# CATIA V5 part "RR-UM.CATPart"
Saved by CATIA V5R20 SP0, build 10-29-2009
Part number: RR-UM
Revision: ANY
Definition: UNKNOWN
Nomenclature: RR-UM
Source: Unknown
Bounding box of the stored display mesh (mm): x -14.408 to 14.38, y 0 to 3, z -14.21 to 14.3
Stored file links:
  C:\Users\Utente\Desktop\IO LAVORO\3D X SITO CF\X SITO\3D files UM\UM064242 PRODUCT\RR-UM.CATPart
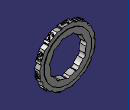
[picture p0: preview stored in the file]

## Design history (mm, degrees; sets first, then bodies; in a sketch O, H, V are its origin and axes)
Body1 "MatrizC2" (main body)
  Solid1: solid without history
